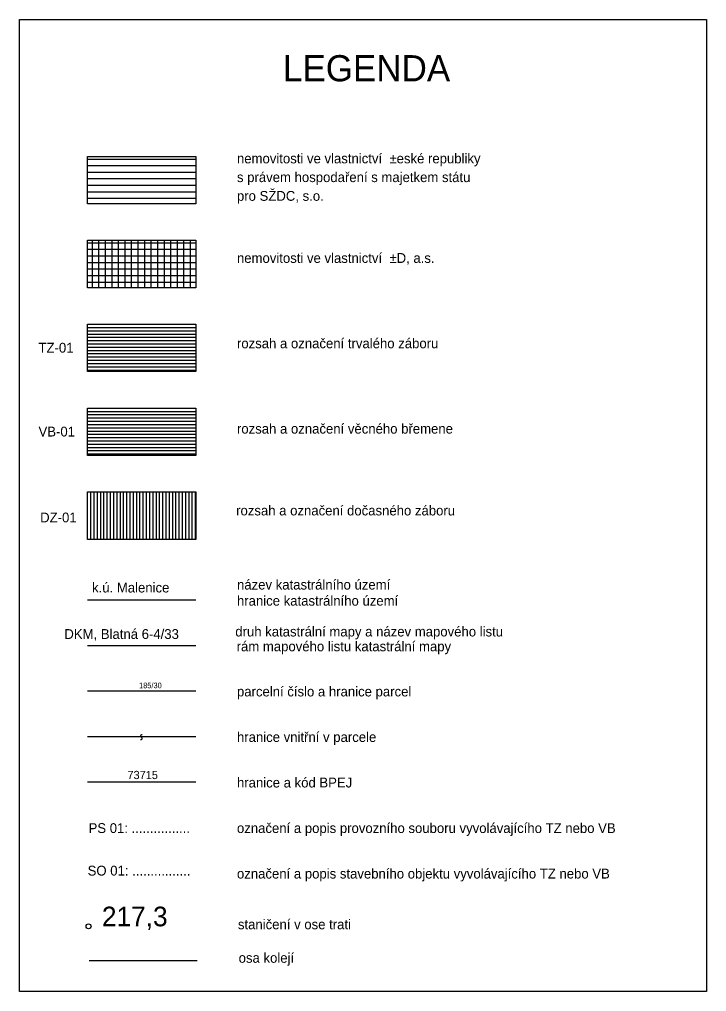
# Model space of a CAD drawing. Extents: x -792659 to -786947, y -1118170 to -1109641.
# Drawn here: x -787157.1 to -786947.1, y -1118169.5 to -1117872.5 of the extents above; entities that cross this region are included whole.
import ezdxf

# ---------------------------------------------------------------- set-up
doc = ezdxf.new("R2010")
doc.units = 0
doc.layers.add('1', color=7, linetype='Continuous')

msp = doc.modelspace()

# ---------------------------------------------------------------- linework, layer by layer
at = {"layer": '1'}
for p, q in [((-787136.25, -1117915.14), (-787103.13, -1117915.14)), ((-787136.25, -1117917.14), (-787103.13, -1117917.14)), ((-787136.25, -1117919.14), (-787103.13, -1117919.14)), ((-787136.25, -1117921.14), (-787103.13, -1117921.14)), ((-787136.25, -1117923.14), (-787103.13, -1117923.14)), ((-787136.25, -1117925.14), (-787103.13, -1117925.14)), ((-787136.25, -1117927.14), (-787103.13, -1117927.14)), ((-787134.86, -1117939.97), (-787134.86, -1117954.45)), ((-787132.86, -1117939.97), (-787132.86, -1117954.45)), ((-787130.86, -1117939.97), (-787130.86, -1117954.45)), ((-787128.86, -1117939.97), (-787128.86, -1117954.45)), ((-787126.86, -1117939.97), (-787126.86, -1117954.45)), ((-787124.86, -1117939.97), (-787124.86, -1117954.45)), ((-787122.86, -1117939.97), (-787122.86, -1117954.45)), ((-787120.86, -1117939.97), (-787120.86, -1117954.45)), ((-787118.86, -1117939.97), (-787118.86, -1117954.45)), ((-787116.86, -1117939.97), (-787116.86, -1117954.45)), ((-787114.86, -1117939.97), (-787114.86, -1117954.45)), ((-787112.86, -1117939.97), (-787112.86, -1117954.45)), ((-787110.86, -1117939.97), (-787110.86, -1117954.45)), ((-787108.86, -1117939.97), (-787108.86, -1117954.45)), ((-787106.86, -1117939.97), (-787106.86, -1117954.45)), ((-787104.86, -1117939.97), (-787104.86, -1117954.45)), ((-787136.25, -1117940.73), (-787103.13, -1117940.73)), ((-787136.25, -1117942.73), (-787103.13, -1117942.73)), ((-787136.25, -1117944.73), (-787103.13, -1117944.73)), ((-787136.25, -1117946.73), (-787103.13, -1117946.73)), ((-787136.25, -1117948.73), (-787103.13, -1117948.73)), ((-787136.25, -1117950.73), (-787103.13, -1117950.73)), ((-787136.25, -1117952.73), (-787103.13, -1117952.73)), ((-787136.21, -1117966.61), (-787103.13, -1117966.61)), ((-787136.21, -1117967.61), (-787103.13, -1117967.61)), ((-787136.21, -1117968.61), (-787103.13, -1117968.61)), ((-787136.21, -1117969.61), (-787103.13, -1117969.61)), ((-787136.21, -1117970.61), (-787103.13, -1117970.61)), ((-787136.21, -1117971.61), (-787103.13, -1117971.61)), ((-787136.21, -1117972.61), (-787103.13, -1117972.61)), ((-787136.21, -1117973.61), (-787103.13, -1117973.61)), ((-787136.21, -1117974.61), (-787103.13, -1117974.61)), ((-787136.21, -1117975.61), (-787103.13, -1117975.61)), ((-787136.21, -1117976.61), (-787103.13, -1117976.61)), ((-787136.21, -1117977.61), (-787103.13, -1117977.61)), ((-787136.21, -1117978.61), (-787103.13, -1117978.61)), ((-787136.21, -1117979.61), (-787103.13, -1117979.61)), ((-787136.21, -1117992.24), (-787103.13, -1117992.24)), ((-787136.21, -1117993.24), (-787103.13, -1117993.24)), ((-787136.21, -1117994.24), (-787103.13, -1117994.24)), ((-787136.21, -1117995.24), (-787103.13, -1117995.24)), ((-787136.21, -1117996.24), (-787103.13, -1117996.24)), ((-787136.21, -1117997.24), (-787103.13, -1117997.24)), ((-787136.21, -1117998.24), (-787103.13, -1117998.24)), ((-787136.21, -1117999.24), (-787103.13, -1117999.24)), ((-787136.21, -1118000.24), (-787103.13, -1118000.24)), ((-787136.21, -1118001.24), (-787103.13, -1118001.24)), ((-787136.21, -1118002.24), (-787103.13, -1118002.24)), ((-787136.21, -1118003.24), (-787103.13, -1118003.24)), ((-787136.21, -1118004.24), (-787103.13, -1118004.24)), ((-787136.21, -1118005.24), (-787103.13, -1118005.24)), ((-787135.21, -1118031.34), (-787135.21, -1118016.86)), ((-787134.21, -1118031.34), (-787134.21, -1118016.86)), ((-787133.21, -1118031.34), (-787133.21, -1118016.86)), ((-787132.21, -1118031.34), (-787132.21, -1118016.86)), ((-787131.21, -1118031.34), (-787131.21, -1118016.86)), ((-787130.21, -1118031.34), (-787130.21, -1118016.86)), ((-787129.21, -1118031.34), (-787129.21, -1118016.86)), ((-787128.21, -1118031.34), (-787128.21, -1118016.86)), ((-787127.21, -1118031.34), (-787127.21, -1118016.86)), ((-787126.21, -1118031.34), (-787126.21, -1118016.86)), ((-787125.21, -1118031.34), (-787125.21, -1118016.86)), ((-787124.21, -1118031.34), (-787124.21, -1118016.86)), ((-787123.21, -1118031.34), (-787123.21, -1118016.86)), ((-787122.21, -1118031.34), (-787122.21, -1118016.86)), ((-787121.21, -1118031.34), (-787121.21, -1118016.86)), ((-787120.21, -1118031.34), (-787120.21, -1118016.86)), ((-787119.21, -1118031.34), (-787119.21, -1118016.86)), ((-787118.21, -1118031.34), (-787118.21, -1118016.86)), ((-787117.21, -1118031.34), (-787117.21, -1118016.86)), ((-787116.21, -1118031.34), (-787116.21, -1118016.86)), ((-787115.21, -1118031.34), (-787115.21, -1118016.86)), ((-787114.21, -1118031.34), (-787114.21, -1118016.86)), ((-787113.21, -1118031.34), (-787113.21, -1118016.86)), ((-787112.21, -1118031.34), (-787112.21, -1118016.86)), ((-787111.21, -1118031.34), (-787111.21, -1118016.86)), ((-787110.21, -1118031.34), (-787110.21, -1118016.86)), ((-787109.21, -1118031.34), (-787109.21, -1118016.86)), ((-787108.21, -1118031.34), (-787108.21, -1118016.86)), ((-787107.21, -1118031.34), (-787107.21, -1118016.86)), ((-787106.21, -1118031.34), (-787106.21, -1118016.86)), ((-787105.21, -1118031.34), (-787105.21, -1118016.86)), ((-787104.21, -1118031.34), (-787104.21, -1118016.86)), ((-787103.21, -1118031.34), (-787103.21, -1118016.86)), ((-787103.13, -1118049.92), (-787136.21, -1118049.92)), ((-787103.13, -1118063.83), (-787136.21, -1118063.83)), ((-787103.13, -1118077.74), (-787136.21, -1118077.74)), ((-787103.13, -1118091.65), (-787136.21, -1118091.65)), ((-787103.13, -1118105.56), (-787136.21, -1118105.56)), ((-787135.77, -1118160), (-787102.69, -1118160))]:
    msp.add_line(p, q, dxfattribs=at)
for points in [[(-787157.05, -1117872.5), (-786947.05, -1117872.5), (-786947.05, -1118169.5), (-787157.05, -1118169.5)], [(-787136.21, -1117914.34), (-787103.13, -1117914.34), (-787103.13, -1117928.82), (-787136.21, -1117928.82)], [(-787136.21, -1117914.34), (-787103.13, -1117914.34), (-787103.13, -1117928.82), (-787136.21, -1117928.82)], [(-787136.21, -1117939.97), (-787103.13, -1117939.97), (-787103.13, -1117954.45), (-787136.21, -1117954.45)], [(-787136.21, -1117965.6), (-787103.13, -1117965.6), (-787103.13, -1117980.08), (-787136.21, -1117980.08)], [(-787136.21, -1117965.6), (-787103.13, -1117965.6), (-787103.13, -1117980.08), (-787136.21, -1117980.08)], [(-787136.21, -1117991.23), (-787103.13, -1117991.23), (-787103.13, -1118005.71), (-787136.21, -1118005.71)], [(-787136.21, -1117991.23), (-787103.13, -1117991.23), (-787103.13, -1118005.71), (-787136.21, -1118005.71)], [(-787136.21, -1118016.86), (-787103.13, -1118016.86), (-787103.13, -1118031.34), (-787136.21, -1118031.34)]]:
    msp.add_lwpolyline(points, close=True, dxfattribs=at)
msp.add_circle((-787135.92, -1118149.56), 0.75, dxfattribs=at)
for centre, start, end in [((-787119.69, -1118091.46), 72.812, 252.812), ((-787119.91, -1118092.18), 252.812, 72.812)]:
    msp.add_arc(centre, 0.375, start, end, dxfattribs=at)

# ---------------------------------------------------------------- texts
for s, height, p in [('LEGENDA', 8, (-787076.52, -1117891.41)), ('nemovitosti ve vlastnictví  ±eské republiky', 3, (-787090.57, -1117916.47)), ('s právem hospodaření s majetkem státu', 3, (-787090.57, -1117922.19)), ('pro SŽDC, s.o.', 3, (-787090.57, -1117927.91)), ('nemovitosti ve vlastnictví  ±D, a.s.', 3, (-787090.57, -1117946.88)), ('rozsah a označení trvalého záboru', 3, (-787090.57, -1117972.96)), ('TZ-01', 3, (-787151.22, -1117974.29)), ('VB-01', 3, (-787151.22, -1117999.92)), ('rozsah a označení věcného břemene', 3, (-787090.57, -1117999.04)), ('rozsah a označení dočasného záboru', 3, (-787090.82, -1118024.03)), ('DZ-01', 3, (-787150.72, -1118026.16)), ('k.ú. Malenice', 3, (-787134.86, -1118047.57)), ('název katastrálního území', 3, (-787090.55, -1118046.68)), ('hranice katastrálního území', 3, (-787090.57, -1118051.6)), ('DKM, Blatná 6-4/33', 3, (-787143.32, -1118061.77)), ('druh katastrální mapy a název mapového listu', 3, (-787091.08, -1118061.01)), ('rám mapového listu katastrální mapy', 3, (-787090.67, -1118065.54)), ('185/30', 1.7, (-787120.5, -1118076.82)), ('parcelní číslo a hranice parcel', 3, (-787090.57, -1118079.33)), ('hranice vnitřní v parcele', 3, (-787090.57, -1118093.24)), ('73715', 2.5, (-787124.03, -1118104.58)), ('hranice a kód BPEJ', 3, (-787090.57, -1118107.15)), ('PS 01: ................', 3, (-787135.92, -1118121.06)), ('označení a popis provozního souboru vyvolávajícího TZ nebo VB', 3, (-787090.57, -1118121.06)), ('SO 01: ................', 3, (-787136.21, -1118134.06)), ('označení a popis stavebního objektu vyvolávajícího TZ nebo VB', 3, (-787090.57, -1118134.97)), ('217,3', 6, (-787131.84, -1118149.56)), ('staničení v ose trati', 3, (-787090.28, -1118150.47)), ('osa kolejí', 3, (-787090.05, -1118160.7))]:
    msp.add_text(s, height=height, dxfattribs=at).set_placement(p)

doc.saveas('drawing.dxf')
